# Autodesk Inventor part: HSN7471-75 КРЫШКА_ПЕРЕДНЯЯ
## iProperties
Created: 2011-02
Part Number: HSN7471-75 КРЫШКА_ПЕРЕДНЯЯ
Document SubType Name: Modeling
Designer: Чернышев Юрий
Mass: 1941.67 g
Surface Area: 1581.88 cm^2
Volume: 1941.67 cm^3
Density: 1 g/cm^3
Author: Чернышев Юрий
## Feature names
1. ExtrusionBlind1
2. ExtrusionBlind2
3. Fillet1
4. Fillet3
5. Hole1
6. Hole2
7. Hole3
8. Hole4
9. Hole5
10. Hole6
11. Hole7
12. Hole8
13. Hole9
14. Hole10
15. Hole11
16. Hole12
17. Hole13
18. Hole14
19. Hole15
20. Hole16
21. AM_HOLE_SI0030_2 [Hole]
